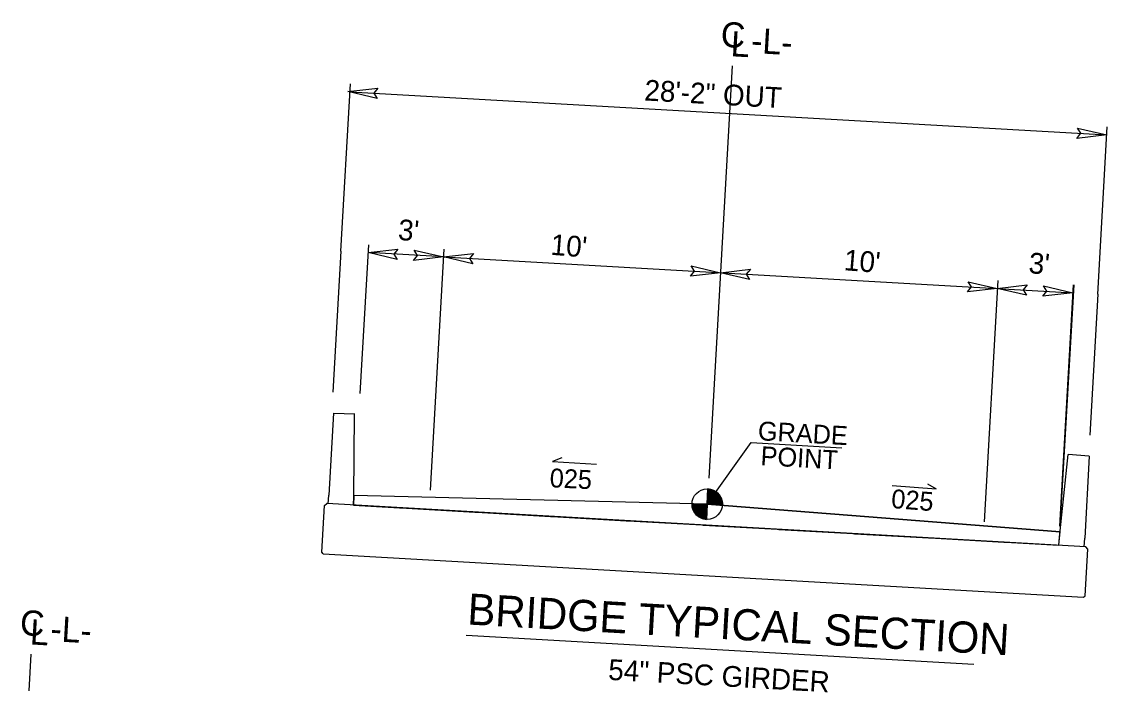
# Model space of a CAD drawing. Extents: x 2604316 to 2606605, y 617090 to 619543.
# Drawn here: x 2606260.3 to 2606604.8, y 617261.6 to 617474.6 of the extents above; entities that cross this region are included whole.
import ezdxf

# ---------------------------------------------------------------- set-up
doc = ezdxf.new("R2010")
doc.units = 0
for name, color, linetype in [('Prop Dimension Text', 7, 'Continuous'), ('Prop Shade Light', 7, 'Continuous'), ('Sheet Data Text CELL', 7, 'Continuous'), ('Typical Grade Point Symbol CELL', 7, 'Continuous'), ('Typical Pavement Slope CELL', 7, 'Continuous'), ('Typical Pavement Slope Information CELL', 7, 'Continuous'), ('Typical Terminator CELL', 7, 'Continuous'), ('Typical Text Centerline CELL', 7, 'Continuous'), ('Typical Text General CELL', 7, 'Continuous'), ('Typical Text Grade Point CELL', 7, 'Continuous'), ('Typical Text Label CELL', 7, 'Continuous')]:
    doc.layers.add(name, color=color, linetype=linetype)

msp = doc.modelspace()

# ---------------------------------------------------------------- linework, layer by layer
at = {"layer": 'Prop Shade Light'}
for p, q in [((2606365.74, 617324.05), (2606365.63, 617321.01)), ((2606365.72, 617323.62), (2606365.73, 617323.62)), ((2606365.72, 617323.62), (2606365.73, 617323.62)), ((2606365.74, 617324.05), (2606365.74, 617324.05)), ((2606365.74, 617324.05), (2606365.74, 617324.05)), ((2606365.63, 617321.01), (2606380.15, 617320.19)), ((2606452.59, 617316.06), (2606476.07, 617314.72)), ((2606476.07, 617314.72), (2606476.57, 617314.7)), ((2606476.57, 617314.7), (2606500.04, 617313.36)), ((2606500.04, 617313.36), (2606500.54, 617313.33)), ((2606500.54, 617313.33), (2606524.02, 617311.99)), ((2606524.02, 617311.99), (2606524.52, 617311.96)), ((2606524.52, 617311.96), (2606548, 617310.63)), ((2606589.42, 617308.27), (2606589.79, 617312.57)), ((2606589.43, 617308.27), (2606589.42, 617308.27)), ((2606589.43, 617308.27), (2606589.43, 617308.27)), ((2606589.62, 617310.87), (2606589.61, 617310.87)), ((2606589.62, 617310.87), (2606589.61, 617310.87))]:
    msp.add_line(p, q, dxfattribs=at)
for points in [[(2606477.83, 617321.34), (2606477.83, 617321.34), (2606365.74, 617324.05)], [(2606380.15, 617320.19), (2606380.65, 617320.16), (2606404.13, 617318.82), (2606404.63, 617318.79), (2606428.11, 617317.46), (2606428.61, 617317.43), (2606452.09, 617316.09), (2606452.59, 617316.06)], [(2606589.79, 617312.57), (2606589.79, 617312.57), (2606477.83, 617321.34)], [(2606548, 617310.63), (2606548.5, 617310.6), (2606571.98, 617309.26), (2606572.48, 617309.23), (2606589.43, 617308.27)]]:
    msp.add_lwpolyline(points, dxfattribs=at)
at = {"layer": 'Sheet Data Text CELL'}
for p, q in [((2606359.29, 617350.25), (2606357.73, 617324.22)), ((2606359.29, 617350.25), (2606365.98, 617350.02)), ((2606365.73, 617323.62), (2606365.96, 617350.02)), ((2606589.61, 617310.87), (2606592.38, 617337.12)), ((2606599.03, 617336.59), (2606592.36, 617337.13)), ((2606599.03, 617336.59), (2606597.63, 617310.56)), ((2606357.58, 617321.47), (2606357.73, 617324.22)), ((2606365.63, 617321.01), (2606365.72, 617323.62)), ((2606355.54, 617306.05), (2606356.39, 617320.87)), ((2606356.39, 617320.87), (2606357.09, 617321.5)), ((2606597.96, 617307.78), (2606357.09, 617321.5)), ((2606589.42, 617308.27), (2606589.62, 617310.87)), ((2606597.47, 617307.81), (2606597.63, 617310.56)), ((2606356.01, 617305.52), (2606355.54, 617306.05)), ((2606356.01, 617305.52), (2606597.21, 617291.79)), ((2606597.74, 617292.26), (2606598.59, 617307.08)), ((2606598.59, 617307.08), (2606597.96, 617307.78)), ((2606597.21, 617291.79), (2606597.74, 617292.26))]:
    msp.add_line(p, q, dxfattribs=at)
at = {"layer": 'Typical Grade Point Symbol CELL'}
for p, q in [((2606477.83, 617321.34), (2606478.05, 617326.17)), ((2606473, 617321.56), (2606477.83, 617321.34)), ((2606477.6, 617316.51), (2606477.83, 617321.34)), ((2606477.83, 617321.34), (2606477.6, 617316.51)), ((2606482.66, 617321.13), (2606477.83, 617321.34))]:
    msp.add_line(p, q, dxfattribs=at)
for points in [[(2606478.09, 617326.17), (2606478.09, 617326.17), (2606477.87, 617321.34)], [(2606478.19, 617326.17), (2606477.97, 617321.34)], [(2606478.28, 617326.15), (2606478.07, 617321.33)], [(2606478.38, 617326.15), (2606478.16, 617321.33)], [(2606478.48, 617326.13), (2606478.26, 617321.32)], [(2606478.57, 617326.12), (2606478.36, 617321.32)], [(2606478.67, 617326.1), (2606478.45, 617321.31)], [(2606478.76, 617326.09), (2606478.55, 617321.31)], [(2606478.86, 617326.07), (2606478.65, 617321.31)], [(2606478.96, 617326.05), (2606478.74, 617321.3)], [(2606479.05, 617326.02), (2606478.84, 617321.3)], [(2606479.15, 617325.99), (2606478.94, 617321.29)], [(2606479.24, 617325.97), (2606479.03, 617321.29)], [(2606479.34, 617325.93), (2606479.13, 617321.28)], [(2606479.43, 617325.9), (2606479.23, 617321.28)], [(2606479.53, 617325.87), (2606479.32, 617321.28)], [(2606479.62, 617325.83), (2606479.42, 617321.27)], [(2606479.72, 617325.8), (2606479.52, 617321.27)], [(2606479.81, 617325.75), (2606479.61, 617321.26)], [(2606479.91, 617325.7), (2606479.71, 617321.26)], [(2606480, 617325.65), (2606479.81, 617321.25)], [(2606480.1, 617325.61), (2606479.9, 617321.25)], [(2606480.19, 617325.56), (2606480, 617321.25)], [(2606480.29, 617325.5), (2606480.1, 617321.24)], [(2606480.38, 617325.44), (2606480.19, 617321.24)], [(2606480.47, 617325.39), (2606480.29, 617321.23)], [(2606480.57, 617325.33), (2606480.39, 617321.23)], [(2606480.66, 617325.26), (2606480.48, 617321.22)], [(2606480.76, 617325.19), (2606480.58, 617321.22)], [(2606480.85, 617325.11), (2606480.68, 617321.21)], [(2606480.94, 617325.04), (2606480.77, 617321.21)], [(2606481.04, 617324.96), (2606480.87, 617321.21)], [(2606481.13, 617324.87), (2606480.97, 617321.2)], [(2606481.22, 617324.78), (2606481.06, 617321.2)], [(2606481.31, 617324.69), (2606481.16, 617321.19)], [(2606481.41, 617324.59), (2606481.25, 617321.19)], [(2606481.5, 617324.49), (2606481.35, 617321.18)], [(2606481.59, 617324.38), (2606481.45, 617321.18)], [(2606481.68, 617324.26), (2606481.54, 617321.18)], [(2606481.77, 617324.13), (2606481.64, 617321.17)], [(2606481.86, 617324), (2606481.74, 617321.17)], [(2606481.96, 617323.86), (2606481.83, 617321.16)], [(2606482.05, 617323.7), (2606481.93, 617321.16)], [(2606482.13, 617323.54), (2606482.03, 617321.15)], [(2606482.22, 617323.36), (2606482.12, 617321.15)], [(2606482.31, 617323.15), (2606482.22, 617321.15)], [(2606482.4, 617322.92), (2606482.32, 617321.14)], [(2606482.48, 617322.65), (2606482.41, 617321.14)], [(2606482.56, 617322.31), (2606482.51, 617321.13)], [(2606482.64, 617321.82), (2606482.61, 617321.13)], [(2606473.02, 617321.56), (2606473, 617321.03)], [(2606473.12, 617321.55), (2606473.07, 617320.46)], [(2606473.22, 617321.55), (2606473.15, 617320.11)], [(2606473.31, 617321.54), (2606473.24, 617319.82)], [(2606473.41, 617321.54), (2606473.32, 617319.59)], [(2606473.51, 617321.54), (2606473.41, 617319.38)], [(2606473.6, 617321.53), (2606473.5, 617319.19)], [(2606473.7, 617321.53), (2606473.59, 617319.02)], [(2606473.8, 617321.52), (2606473.68, 617318.86)], [(2606473.89, 617321.52), (2606473.77, 617318.72)], [(2606473.99, 617321.51), (2606473.86, 617318.58)], [(2606474.09, 617321.51), (2606473.95, 617318.46)], [(2606474.18, 617321.51), (2606474.04, 617318.34)], [(2606474.28, 617321.5), (2606474.13, 617318.23)], [(2606474.38, 617321.5), (2606474.22, 617318.12)], [(2606474.47, 617321.49), (2606474.32, 617318.02)], [(2606474.57, 617321.49), (2606474.41, 617317.93)], [(2606474.67, 617321.48), (2606474.5, 617317.84)], [(2606474.76, 617321.48), (2606474.6, 617317.75)], [(2606474.86, 617321.48), (2606474.69, 617317.67)], [(2606474.96, 617321.47), (2606474.78, 617317.59)], [(2606475.05, 617321.47), (2606474.88, 617317.52)], [(2606475.15, 617321.46), (2606474.97, 617317.45)], [(2606475.25, 617321.46), (2606475.06, 617317.38)], [(2606475.34, 617321.45), (2606475.16, 617317.31)], [(2606475.44, 617321.45), (2606475.25, 617317.25)], [(2606475.54, 617321.44), (2606475.35, 617317.2)], [(2606475.63, 617321.44), (2606475.44, 617317.14)], [(2606475.73, 617321.44), (2606475.53, 617317.09)], [(2606475.83, 617321.43), (2606475.63, 617317.04)], [(2606475.92, 617321.43), (2606475.72, 617317)], [(2606476.02, 617321.42), (2606475.82, 617316.95)], [(2606476.11, 617321.42), (2606475.91, 617316.9)], [(2606476.21, 617321.41), (2606476.01, 617316.86)], [(2606476.31, 617321.41), (2606476.1, 617316.83)], [(2606476.4, 617321.41), (2606476.2, 617316.79)], [(2606476.5, 617321.4), (2606476.29, 617316.77)], [(2606476.6, 617321.4), (2606476.39, 617316.73)], [(2606476.69, 617321.39), (2606476.48, 617316.7)], [(2606476.79, 617321.39), (2606476.58, 617316.68)], [(2606476.89, 617321.38), (2606476.68, 617316.65)], [(2606476.98, 617321.38), (2606476.77, 617316.63)], [(2606477.08, 617321.38), (2606476.87, 617316.61)], [(2606477.18, 617321.37), (2606476.96, 617316.59)], [(2606477.27, 617321.37), (2606477.06, 617316.57)], [(2606477.37, 617321.36), (2606477.16, 617316.56)], [(2606477.47, 617321.36), (2606477.25, 617316.54)], [(2606477.56, 617321.35), (2606477.35, 617316.54)], [(2606477.66, 617321.35), (2606477.44, 617316.52)], [(2606477.76, 617321.35), (2606477.54, 617316.52), (2606477.54, 617316.52)]]:
    msp.add_lwpolyline(points, dxfattribs=at)
msp.add_circle((2606477.83, 617321.34), 4.83, dxfattribs=at)
for start, end in [(357.4284, 87.4284), (177.4284, 267.4284)]:
    msp.add_arc((2606477.83, 617321.34), 4.83, start, end, dxfattribs=at)
at = {"layer": 'Typical Pavement Slope CELL'}
for p, q in [((2606431.7, 617336.01), (2606428.72, 617334.84)), ((2606431.7, 617336.01), (2606428.72, 617334.84)), ((2606428.72, 617334.84), (2606442.7, 617334)), ((2606428.72, 617334.84), (2606442.7, 617334)), ((2606536.53, 617327.31), (2606550.49, 617326.24)), ((2606547.7, 617327.81), (2606550.49, 617326.24)), ((2606477.83, 617321.34), (2606365.74, 617324.05)), ((2606477.83, 617321.34), (2606589.79, 617312.57)), ((2606401.36, 617279.7), (2606562.41, 617270.53)), ((2606401.36, 617279.7), (2606562.41, 617270.53))]:
    msp.add_line(p, q, dxfattribs=at)
at = {"layer": 'Typical Terminator CELL'}
for points in [[(2606373.09, 617450.21), (2606363.82, 617452.35), (2606373.32, 617453.48), (2606372.03, 617451.89)], [(2606595.37, 617440.78), (2606604.63, 617438.64), (2606595.13, 617437.51), (2606596.42, 617439.11)], [(2606379.47, 617399.08), (2606370.2, 617401.22), (2606379.7, 617402.35), (2606378.41, 617400.75)], [(2606384.89, 617402), (2606394.16, 617399.86), (2606384.66, 617398.73), (2606385.95, 617400.32)], [(2606403.43, 617397.71), (2606394.16, 617399.86), (2606403.67, 617400.98), (2606402.38, 617399.39)], [(2606472.75, 617397), (2606482.02, 617394.85), (2606472.51, 617393.72), (2606473.8, 617395.32)], [(2606491.28, 617392.71), (2606482.02, 617394.85), (2606491.52, 617395.98), (2606490.23, 617394.38)], [(2606560.61, 617391.99), (2606569.88, 617389.85), (2606560.37, 617388.72), (2606561.66, 617390.32)], [(2606579.14, 617387.7), (2606569.88, 617389.85), (2606579.38, 617390.98), (2606578.09, 617389.38)], [(2606584.57, 617390.63), (2606593.84, 617388.48), (2606584.33, 617387.35), (2606585.62, 617388.95)]]:
    msp.add_lwpolyline(points, close=True, dxfattribs=at)
at = {"layer": 'Typical Text Centerline CELL'}
for p, q in [((2606485.76, 617460.52), (2606478.3, 617329.6)), ((2606262.68, 617262), (2606263.34, 617273.68))]:
    msp.add_line(p, q, dxfattribs=at)
at = {"layer": 'Typical Text Grade Point CELL'}
for p, q in [((2606477.83, 617321.34), (2606491.74, 617340.9)), ((2606491.74, 617340.9), (2606520.5, 617339.26))]:
    msp.add_line(p, q, dxfattribs=at)
at = {"layer": 'Typical Text Label CELL'}
for p, q in [((2606361.61, 617401.71), (2606364.64, 617454.81)), ((2606364.5, 617452.31), (2606604.63, 617438.64)), ((2606601.75, 617388.03), (2606604.78, 617441.13)), ((2606361.61, 617401.71), (2606359.06, 617356.94)), ((2606370.34, 617403.72), (2606367.65, 617356.45)), ((2606394.16, 617399.86), (2606370.2, 617401.22)), ((2606394.3, 617402.35), (2606389.94, 617325.75)), ((2606394.16, 617399.86), (2606569.88, 617389.85)), ((2606570.02, 617392.34), (2606565.66, 617315.75)), ((2606593.98, 617390.98), (2606589.62, 617314.38)), ((2606594.11, 617390.97), (2606589.75, 617314.37)), ((2606569.88, 617389.85), (2606593.84, 617388.48)), ((2606601.75, 617388.03), (2606599.2, 617343.26)), ((2606597.96, 617307.78), (2606357.09, 617321.5))]:
    msp.add_line(p, q, dxfattribs=at)

# ---------------------------------------------------------------- texts
at = {"layer": 'Prop Dimension Text'}
for s, p in [('GRADE', (2606493.78, 617341.68)), ('POINT', (2606494.64, 617333.75))]:
    msp.add_text(s, height=6, rotation=356.7403, dxfattribs=at).set_placement(p)
at = {"layer": 'Typical Pavement Slope CELL'}
for s, height, rotation, p in [('28\'-2" OUT', 6.6, 356.7403, (2606457.77, 617449.56)), ("3'", 6.6, 355.4447, (2606379.55, 617405.29)), ("10'", 6.6, 355.4447, (2606427.96, 617400.56)), ("10'", 6.6, 355.4447, (2606521.03, 617395.66)), ("3'", 6.6, 355.4447, (2606579.65, 617394.72)), ('BRIDGE TYPICAL SECTION', 9.9, 356.7403, (2606401.56, 617283.13)), ('BRIDGE TYPICAL SECTION', 9.9, 356.7403, (2606401.56, 617283.13))]:
    msp.add_text(s, height=height, rotation=rotation, dxfattribs=at).set_placement(p)
at = {"layer": 'Typical Pavement Slope Information CELL'}
for rotation, p in [(357.258, (2606427.74, 617326.72)), (355.5945, (2606536.06, 617320.13))]:
    msp.add_text('025', height=6, rotation=rotation, dxfattribs=at).set_placement(p)
at = {"layer": 'Typical Text Centerline CELL'}
for s, rotation, p in [('C', 356.7403, (2606481.96, 617466.6)), ('C', 356.7403, (2606481.96, 617466.6)), ('L', 356.6872, (2606485.13, 617463.61)), ('L', 356.6872, (2606485.13, 617463.61)), ('-L-', 356.6872, (2606491.61, 617464.66)), ('-L-', 356.6872, (2606491.61, 617464.66)), ('C', 356.7403, (2606259.61, 617279.79)), ('L', 356.6872, (2606262.78, 617276.81)), ('-L-', 356.6872, (2606269.26, 617277.86))]:
    msp.add_text(s, height=8, rotation=rotation, dxfattribs=at).set_placement(p)
at = {"layer": 'Typical Text General CELL'}
msp.add_text('54" PSC GIRDER', height=6.6, rotation=356.7403, dxfattribs=at).set_placement((2606446.29, 617265.56))

doc.saveas('drawing.dxf')
